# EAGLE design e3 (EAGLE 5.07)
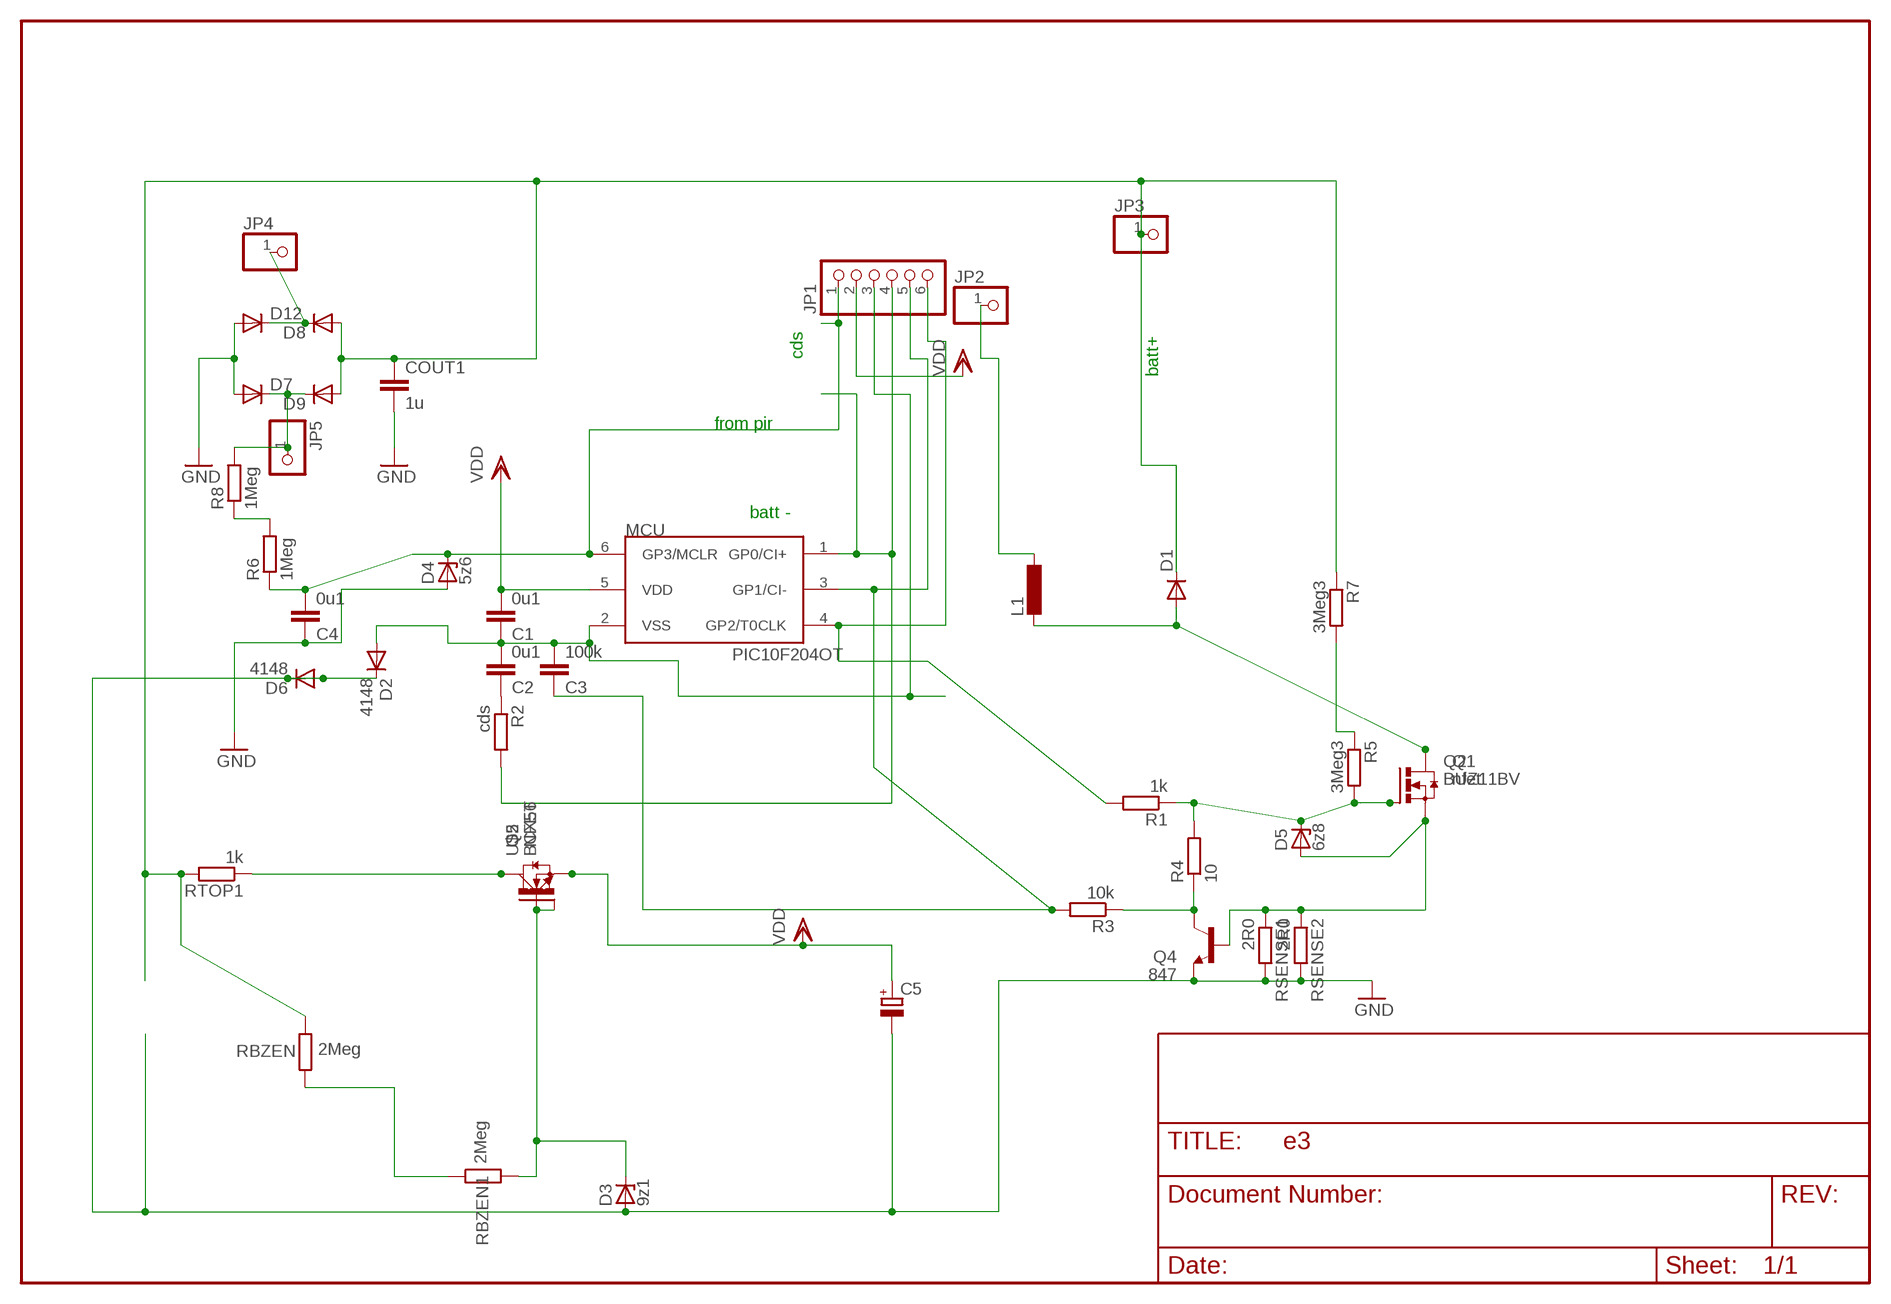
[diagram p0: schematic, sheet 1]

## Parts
C1  0u1  C-EUC0805  [C0805]
C2  0u1  C-EUC0805  [C0805]
C3  100k  C-EUC0805  [C0805]
C4  0u1  C-EUC1206  [C1206]
C5  CPOL-EUSANYO_SMD_C6  [SANYO-OSCON_SMD_C6]
COUT1  1u  C-EU075-032X103  [C075-032X103]
D1  DIODE-SMC  [SMC]
D2  4148  1N4148MINIMELF  [MINIMELF]
D3  9z1  ZENER-DIODESOD80C  [SOD80C]
D4  5z6  ZENER-DIODESOD80C  [SOD80C]
D5  6z8  ZENER-DIODESOD80C  [SOD80C]
D6  4148  1N4148MINIMELF  [MINIMELF]
D7  DIODE-DO214AA  [DO214AA]
D8  DIODE-DO214AA  [DO214AA]
D9  DIODE-DO214AA  [DO214AA]
D12  DIODE-DO214AA  [DO214AA]
JP1  PINHD-1X6  [1X06BOX]
JP2  PINHD-1X11MM6  [1X1MM8]
JP3  PINHD-1X11MM6  [1X1MM8]
JP4  PINHD-1X11MM6  [1X1MM8]
JP5  PINHD-1X11MM6  [1X1MM8]
L1  L-EUPIS2816  [PIS2816]
MCU  PIC10F204OT  [SOT23-6]
Q1  nfet  N-HEXFET_DPAK-  [TO252]
Q2  BUZ11BV  [TO220BV]
Q4  847  BC847ASMD  [SOT23]
Q5  NFET  N-HEXFET_DPAK-  [TO252]
R1  1k  R-EU_R0805  [R0805]
R2  cds  R-EU_0204/2V  [0204V]
R3  10k  R-EU_R0805  [R0805]
R4  10  R-EU_R1206  [R1206]
R5  3Meg3  R-EU_R1206  [R1206]
R6  1Meg  R-EU_R1206  [R1206]
R7  3Meg3  R-EU_R1206  [R1206]
R8  1Meg  R-EU_R1206  [R1206]
RBZEN  2Meg  R-EU_R1206  [R1206]
RBZEN1  2Meg  R-EU_R1206  [R1206]
RSENSE1  2R0  R-EU_R1210  [R1210]
RSENSE2  2R0  R-EU_R2512  [R2512]
RTOP1  1k  R-EU_R1206  [R1206]
U$2  BCX56  [SOT223]

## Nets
AC1: D8.C D12.C JP4.1
AC2: D7.C D9.C JP5.1 R8.2
C: Q5.3(D) RTOP1.1 U$2.2(C)
CB: D3.C Q5.1(G) RBZEN1.2 U$2.1(B)
GND: C4.1 C5.- COUT1.2 D2.C D3.A D4.A D6.A D6.C D7.A D12.A Q4.2(E) RSENSE1.2 RSENSE2.2
HOT: D1.A L1.2 Q1.3(D) Q2.D
LED-: JP2.1 L1.1
N$1: Q4.3(C) R3.1 R4.1
N$2: JP1.4 MCU.1(GP0/CI+) R2.2
N$3: C4.2 D4.C JP1.1 MCU.6(GP3/MCLR) R6.1
N$4: R5.1 R7.2
N$5: C3.1 JP1.5 MCU.3(GP1/CI-) R3.2
N$6: RBZEN1.1 RBZEN.2
N$7: D5.C Q1.1(G) Q2.G R1.1 R4.2 R5.2
N$8: C2.1 R2.1
N$9: R6.2 R8.1
N$14: JP1.6 MCU.4(GP2/T0CLK) R1.2
N$17: D5.A Q1.2(S) Q2.S Q4.1(B) RSENSE1.1 RSENSE2.1
VDD: C1.2 C5.+ JP1.2 MCU.5(VDD) Q5.2(S) U$2.3(E)
VPLUS: COUT1.1 D1.C D8.A D9.A JP3.1 R7.1 RBZEN.1 RTOP1.2
VSS: C1.1 C2.2 C3.2 D2.A JP1.3 MCU.2(VSS)

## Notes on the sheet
- cds
- batt+
- from pir
- batt -

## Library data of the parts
C1-C4 COUT1 = rcl:C-EU: CAPACITOR, European symbol
C5 = rcl-2:CPOL-EU: POLARIZED CAPACITOR, European symbol
D1 = diode-1:DIODE-: DIODE
D2 D6 = diode-1:1N4148: DIODE
D3-D5 = diode:ZENER-DIODE: Z-Diode
D7-D9 D12 = diode:DIODE-: DIODE
JP1 = pinhead:PINHD-1X6: PIN HEADER
JP2-JP5 = pinhead:PINHD-1X1: PIN HEADER
L1 = rcl:L-EU: INDUCTOR, European symbol
MCU = microchip-3:PIC10F2*: uPC nW 0,25/0,5k Program Flash memory Comparator
Q1 Q5 = transistor-power:N-HEXFET_?-*: HEXFET® Power MOSFET
Q2 = transistor-power:BUZ11: N-CHANNEL MOS FET
Q4 = transistor-npn:BC847*: NPN Transistor
R1-R5 R7 RBZEN RBZEN1 RSENSE1 RSENSE2 RTOP1 = rcl:R-EU_: RESISTOR, European symbol
R6 R8 = rcl-2:R-EU_: RESISTOR, European symbol
U$2 = transistor-power:BCX56

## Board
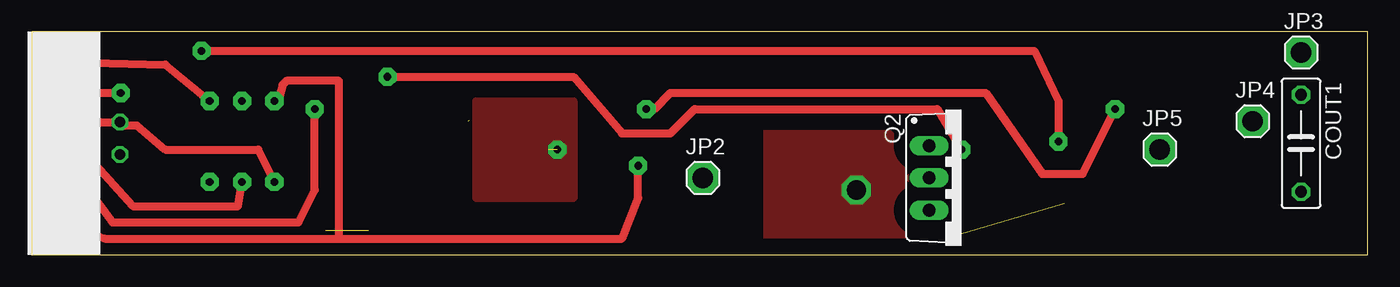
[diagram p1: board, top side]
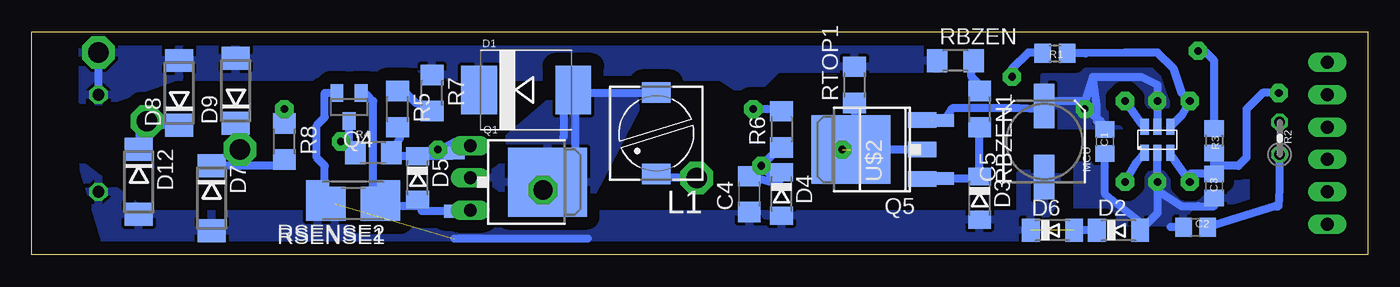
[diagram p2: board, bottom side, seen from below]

Size 104.93 x 17.5 mm. Coordinates in mm from the lower left corner, seen from the top.
Outline: 0,0 104.93,0 104.93,17.5 0,17.5 0,0
Copper layers (1*16): Top 0.035mm / dielectric 1.5mm / Bottom 0.035mm
Design rules "default *": minimum track width 10mil, minimum drill 24mil, track to track 8mil, track to pad 8mil, pad to pad 8mil, via to via 8mil, smd to smd 8mil, copper to edge 20mil, drill to drill 8mil, minimum pad ring 10mil, minimum via ring 8mil, stop-mask expansion 4mil, vias tented up to drill 0mil, thermal gap 10mil

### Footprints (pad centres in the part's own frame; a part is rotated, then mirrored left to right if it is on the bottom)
C0805 = smd 1.3 x 1.5: 1 -0.95,0; 2 0.95,0
C1206 = smd 1.6 x 1.8: 1 -1.4,0; 2 1.4,0
SANYO-OSCON_SMD_C6 = smd 3.5 x 1.6: + 2.8,0; - -2.8,0
C075-032X103 = drill 0.914 octagon: 1 -3.81,0; 2 3.81,0
SMC = smd 2.8 x 3.8: A 3.7,0; C -3.7,0
MINIMELF = smd 1.4 x 1.8: A 1.7,0; C -1.7,0
SOD80C = smd 1.4 x 1.8: A 1.7,0; C -1.7,0
DO214AA = smd 1.8 x 2.2: A 2.55,0; C -2.55,0
1X06BOX = drill 1.016 long: 1 -6.35,0; 2 -3.81,0; 3 -1.27,0; 4 1.27,0; 5 3.81,0; 6 6.35,0
1X1MM8 = drill 1.6 pad 2.54 octagon: 1 0,0
PIS2816 = smd 2.2 x 1.6: 1 0,3.2; 2 0,-3.2
SOT23-6 = smd 0.635 x 1.27: 1 -1.016,-1.016; 2 0,-1.016; 3 1.016,-1.016; 4 1.016,1.016; 5 0,1.016; 6 -1.016,1.016
TO252 = smd 1 x 1.6: 1 -2.28,-3.53; 2 2.28,-3.53 | smd 5.4 x 6.2: 3 0,3.77
TO220BV = drill 1.016 long: D 0,-2.54; G -2.54,-2.54; S 2.54,-2.54
SOT23 = smd 1 x 1.4: 1 -0.95,-1.1; 2 0.95,-1.1; 3 0,1.1
R0805 = smd 1.3 x 1.5: 1 -0.95,0; 2 0.95,0
0204V = drill 0.813 octagon: 1 -1.27,0; 2 1.27,0
R1206 = smd 1.6 x 1.803: 1 -1.422,0; 2 1.422,0
R1210 = smd 1.6 x 2.7: 1 -1.4,0; 2 1.4,0
R2512 = smd 1.8 x 3.2: 1 -2.8,0; 2 2.8,0
SOT223 = smd 1.219 x 2.235: 1 -2.311,-3.099; 2 0,-3.099; 3 2.311,-3.099 | smd 3.6 x 2.2: 4 0,3.099

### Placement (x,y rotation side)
C1  20.64,8.89 90 bottom
C2  13.53,2.16 180 bottom
C3  12.06,5.4 270 bottom
C4  48.58,4.76 90 bottom
C5  25.4,8.89 90 bottom
COUT1  99.69,8.75 270 top
D1  66.1,12.94 0 bottom
D2  19.57,1.91 0 bottom
D3  30.48,4.45 270 bottom
D4  46.04,4.76 270 bottom
D5  74.61,6.03 270 bottom
D6  24.77,1.91 0 bottom
D7  90.81,4.45 270 bottom
D8  93.34,12.7 90 bottom
D9  88.9,12.88 90 bottom
D12  96.52,5.71 270 bottom
JP1  3.17,8.75 90 top
JP2  52.7,6.03 0 top
JP3  99.69,15.88 0 top
JP4  95.89,10.48 0 top
JP5  88.58,8.26 0 top
L1  55.88,9.53 180 bottom
MCU  16.51,9.03 0 bottom
Q1  68.2,5.7 270 bottom
Q2  73.03,6.03 270 top
Q4  80.01,11.6 180 bottom
Q5  36.83,8.26 90 bottom
R1  24.57,15.81 0 bottom
R2  6.92,9.14 90 bottom
R3  12.06,8.95 270 bottom
R4  78.11,8 0 bottom
R5  76.2,11.43 270 bottom
R6  46.04,9.84 90 bottom
R7  73.5,12.7 270 bottom
R8  85.09,8.89 270 bottom
RBZEN  32.38,15.24 0 bottom
RBZEN1  30.48,11.43 270 bottom
RSENSE1  79.69,4 180 bottom
RSENSE2  79.69,4.25 180 bottom
RTOP1  40.32,13.34 90 bottom
U$2  38.1,8.26 90 bottom

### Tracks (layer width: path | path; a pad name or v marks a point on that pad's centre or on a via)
AC1
  Bottom 0.61: D8.C 95.56,10.15 JP4.1 96.51,9.85 D12.C
AC2
  Bottom 0.61: D9.C 88.58,9.7 JP5.1 88.58,6.99 | 88.58,6.99 D7.C | 88.58,6.99 85.57,6.99 R8.2
C  (via drill 0.6 pad 1.42)  (1 unrouted)
  Bottom 0.61: 40.01,8.26 40.51,9.27 | 40.51,9.27 40.64,9.53 40.64,10.16 41.27,10.16 | U$2.2 39.37,8.26 | 39.37,8.26 40.01,8.26 | 39.37,8.26 41.91,9.53 | 40.01,8.26 Q5.3 | RTOP1.1 40.17,9.61 40.51,9.27
  other vias: 41.27,8.26
  pour Top (isolate 0.61, rank 4): 34.92,12.06 42.55,12.06 42.55,4.45 34.92,4.45
CB
  Bottom 0.61: RBZEN1.2 D3.C 30.65,5.97 Q5.1 33.33,5.94 U$2.1
GND  (2 unrouted)
  Bottom 0.61: 61.28,1.27 71.75,1.27 | D2.C D6.A | RSENSE1.2 81.57,3.57 RSENSE2.2 81.92,4.31 81.92,6.99 82.55,7.62 82.55,10.16 81.92,10.79 81.92,12.7 Q4.2
  pour Bottom (isolate 1.016, rank 4): 27.3,3.17 95.89,3.17 100.97,6.99 99.06,0.64 25.72,0.64 25.72,2.54 24.77,3.81 24.13,6.35 27.3,6.35
HOT  (via drill 1.5 pad 1.42)
  Bottom 0.61: 62.23,11.43 62.23,6.35 64.43,6.35 Q1.3 | 62.23,11.43 62.23,12.13 D1.A 63.04,12.72 L1.2 | 63.18,9.21 63.18,11.11 62.87,11.43 62.23,11.43
  other vias: 64.77,5.08
  pour Bottom (isolate 1.27): 57.15,12.06 64.14,12.06 68.58,8.26 69.22,8.26 69.22,3.49 61.59,3.49
  pour Top (isolate 1.27): 57.78,10.16 66.67,10.16 68.58,8.26 68.58,1.27 57.78,1.27
LED-
  Bottom 0.61: JP2.1 55.88,6.03 L1.1
N$1  (via drill 0.6 pad 1.42)
  Top 0.61: v80.64,8.89 80.64,12.06 78.74,16 v13.34,16
  Bottom 0.61: Q4.3 80.01,8.3 R4.1 79.75,8 v80.64,8.89 | R3.1 12.06,15.24 12.82,16 v13.34,16
N$2  (via drill 0.6 pad 1.42)
  Top 0.61: v19.05,5.71 17.78,8.26 10.48,8.26 8.26,10.16 7.18,10.16 R2.2 5.33,10.41 5.08,10.16 3.31,10.16 JP1.4
  Bottom 0.61: MCU.1 18.16,7.24 v19.05,5.71
N$3  (via drill 0.6 pad 1.42)
  Top 0.61: JP1.1 5.71,1.27 24.13,1.27 | 24.13,1.27 24.13,13.65 20,13.65 19.68,13.34 19.37,12.06 v19.05,12.06 | v47.62,6.99 47.62,4.45 46.35,1.27 24.13,1.27
  Bottom 0.61: v19.05,12.06 17.78,10.3 MCU.6 | C4.2 46.34,5.53 D4.C 46.47,5.83 v47.62,6.99 46.83,7.79 R6.1
N$4
  Bottom 0.61: R7.2 74.78,11.91 75.56,12.7 76.05,12.7 R5.1
N$5  (via drill 0.6 pad 1.42)
  Top 0.61: JP1.5 4.45,12.7 v6.99,12.7
  Bottom 0.61: 12.06,6.99 C3.1 13.97,6.35 v13.97,5.71 15.49,7.87 MCU.3 | 12.06,6.99 R3.2 | v6.99,12.7 8.26,12.7 9.53,11.43 9.53,7.62 10.16,6.99 12.06,6.99
N$6
  Bottom 0.61: RBZEN1.1 30.48,13.34 31.11,13.97 31.11,15.09 RBZEN.2
N$7  (via drill 0.6 pad 1.42)
  Top 0.61: v73.03,8.26 71.12,11.43 52.07,11.43 50.16,9.53 46.35,9.53 42.55,13.97 v27.94,13.97
  Bottom 0.61: R5.2 76.03,9.4 76.03,9.11 R4.2 76.42,7.73 D5.C 71.99,7.73 Q1.1 71.73,8.87 v73.03,8.26 71.75,8.57 Q2.G | v27.94,13.97 27.94,14.61 26.67,15.88 25.59,15.88 R1.1
N$8
  Bottom 0.61: R2.1 6.92,5.14 6.99,3.81 7.24,3.81 C2.1
N$9  (via drill 0.6 pad 1.42)
  Top 0.61: v85.09,11.43 82.55,6.35 79.38,6.35 74.93,12.7 50.16,12.7 48.9,11.43 v48.26,11.43
  Bottom 0.61: v85.09,11.43 R8.1 | v48.26,11.43 47.14,11.43 R6.2
N$14  (via drill 0.6 pad 1.42)
  Top 0.61: JP1.6 10.48,14.92 v13.97,12.06
  Bottom 0.61: MCU.4 14.61,10.94 v13.97,12.06 14.61,12.7 15.24,14.61 16.51,15.88 19.05,15.88 22.16,15.81 R1.2
N$17
  Bottom 0.61: Q4.1 78.57,12.53 78.11,12.06 78.11,4.48 RSENSE1.1 78.29,3.81 76.89,3.81 | Q2.S 71.73,3.49 Q1.2 74.3,3.42 74.3,3.81 74.61,3.81 | 74.61,3.81 76.89,3.81 | 76.89,3.81 RSENSE2.1 | 74.61,3.81 D5.A
VDD  (via drill 0.6 pad 1.42)  (1 unrouted)
  Top 0.61: JP1.2 4.58,4.94 6.35,2.54 20.95,2.54 22.23,5.08 v22.23,11.43
  Bottom 0.61: U$2.3 34.34,10.54 | 34.28,10.54 Q5.2 32.65,11.49 27.3,11.49 26.04,11.43 C5.+ 25.4,12.06 22.23,12.06 21.59,13.97 | MCU.5 v16.51,12.06 16.51,13.34 17.78,13.97 21.59,13.97 | 21.59,13.97 21.27,11.75 21.27,10.48 20.95,10.16 C1.2 20.96,10.48 v22.23,11.43
  pour Bottom (isolate 0.813, rank 2): 24.77,10.16 13.34,10.16 13.34,13.97 13.97,14.61 24.77,14.61 26.04,13.34
VPLUS
  Bottom 0.61: COUT1.1 JP3.1
  pour Bottom (isolate 1.016, rank 3): 100.97,12.06 99.06,12.06 93.66,13.97 81.92,13.97 81.28,14.61 74.3,14.61 73.66,13.97 50.8,13.97 48.9,12.7 48.26,12.7 46.35,14.61 33.66,14.61 34.92,16.51 100.97,16.51
VSS  (via drill 0.6 pad 1.42)
  Top 0.61: JP1.3 4.58,7.48 7.94,3.81 16.19,3.81 v16.51,5.71
  Bottom 0.61: C1.1 20.64,4.76 17.51,2.27 | 17.51,2.27 16.51,3.27 16.51,5.08 | 17.51,2.27 D2.A | 16.51,5.08 v16.51,5.71 MCU.2 | C2.2 15.49,2.16 | 16.51,5.08 14.61,3.81 13.34,3.81 12.06,3.81 C3.2
  pour Bottom (isolate 0.813): 9.53,6.99 22.86,6.99 22.86,2.54 9.53,2.54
